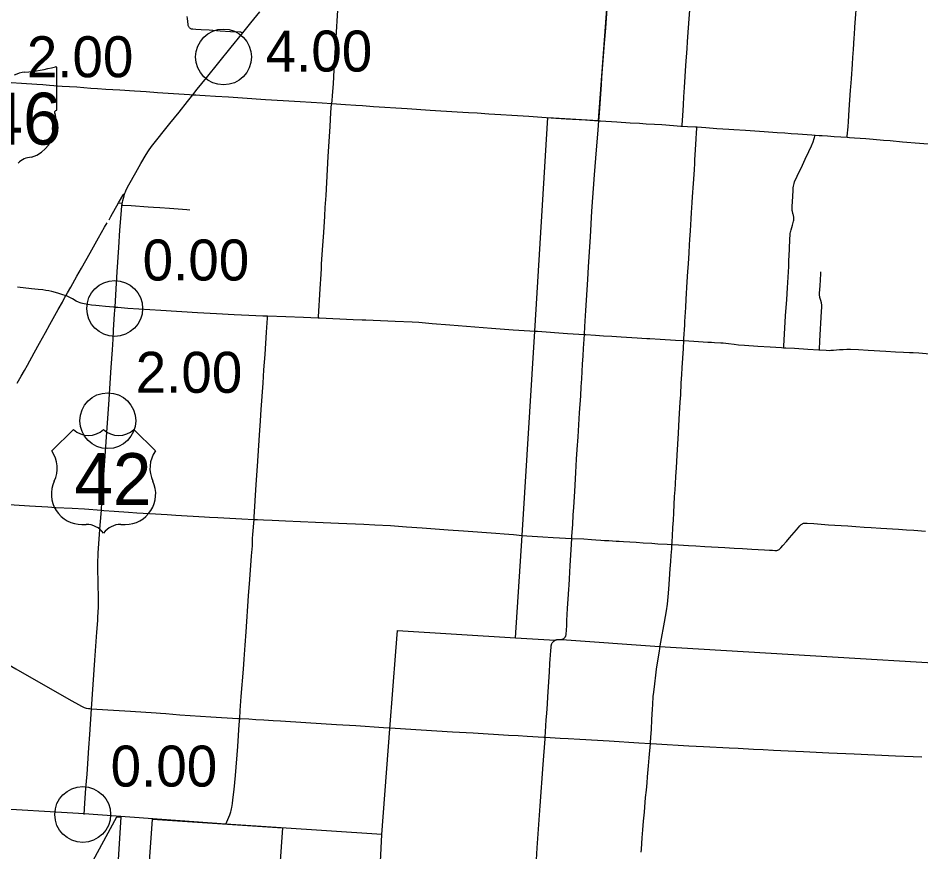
# Model space of a CAD drawing. Extents: x 1813937 to 1948437, y 826606 to 1022856.
# Drawn here: x 1840375 to 1864627, y 879389 to 901785 of the extents above; entities that cross this region are included whole.
import ezdxf

# ---------------------------------------------------------------- set-up
doc = ezdxf.new("R2010")
doc.units = 0
for name, color, linetype in [('Default', 7, 'Continuous'), ('GM_X_Corporation', 7, 'Continuous'), ('GM_X_County', 7, 'Continuous'), ('GM_X_County_Road', 7, 'Continuous'), ('GM_X_State_Route', 7, 'Continuous'), ('GM_X_State_Shield', 7, 'Continuous'), ('GM_X_Township', 7, 'Continuous'), ('GM_X_Township_Road', 7, 'Continuous'), ('GM_X_US_Route', 7, 'Continuous'), ('GM_X_US_Shield', 7, 'Continuous')]:
    doc.layers.add(name, color=color, linetype=linetype)

msp = doc.modelspace()

# ---------------------------------------------------------------- linework, layer by layer
at = {"layer": 'Default'}
for centre in [(1845895, 900740), (1842971, 893987), (1842785, 890971), (1842112, 880395), (1842112, 880395)]:
    msp.add_circle(centre, 750, dxfattribs=at)
at = {"layer": 'GM_X_Corporation'}
for points in [[(1842276, 878944), (1843026, 880333), (1843137, 880326), (1843037, 878758)], [(1843894, 879006), (1843983, 880269), (1847478, 880034), (1847407, 879013)]]:
    msp.add_lwpolyline(points, dxfattribs=at)
at = {"layer": 'GM_X_County'}
msp.add_lwpolyline([(1849106, 864311), (1849634, 872258), (1850017, 877290), (1850147, 879854), (1845959, 880135), (1842150, 880416), (1839410, 880574)], dxfattribs=at)
at = {"layer": 'GM_X_County_Road'}
for points in [[(1858212, 898884), (1858214, 898917), (1858231, 899163), (1858248, 899458), (1858261, 899671), (1858275, 899917), (1858313, 900507), (1858345, 900966), (1858358, 901146), (1858377, 901408), (1858411, 901883), (1858428, 902112), (1858441, 902276), (1858454, 902472), (1858476, 902784), (1858493, 903029), (1858508, 903226), (1858530, 903553), (1858543, 903734), (1858565, 904030)], [(1862739, 899846), (1862745, 899941), (1862761, 900154), (1862770, 900284), (1862779, 900415), (1862787, 900546), (1862798, 900726), (1862812, 900939), (1862834, 901250), (1862840, 901348), (1862854, 901544), (1862879, 901888), (1862912, 902329), (1862927, 902542), (1862942, 902755), (1862964, 903049), (1862969, 903131), (1862980, 903294), (1862992, 903458), (1863006, 903638), (1863012, 903726)], [(1848803, 899489), (1848805, 899500), (1848812, 899560), (1848824, 899707), (1848844, 900018), (1848868, 900395), (1848879, 900591), (1848896, 900853), (1848922, 901263), (1848968, 902000), (1849011, 902721), (1849025, 902966), (1849028, 903004)], [(1855976, 899029), (1855991, 899228), (1856045, 899997), (1856058, 900193), (1856127, 901109), (1856159, 901518), (1856179, 901779), (1856205, 902139), (1856232, 902508)], [(1862645, 898582), (1862647, 898616), (1862668, 898861), (1862679, 899009), (1862701, 899319), (1862739, 899846)], [(1848439, 893732), (1848441, 893763), (1848490, 894516), (1848516, 894909), (1848524, 895057), (1848530, 895171), (1848556, 895564), (1848586, 896023), (1848613, 896465), (1848628, 896694), (1848647, 897022), (1848665, 897366), (1848707, 898070), (1848754, 898873), (1848774, 899250), (1848778, 899288), (1848782, 899332), (1848785, 899370), (1848787, 899396), (1848798, 899459), (1848803, 899489)], [(1854556, 899117), (1854822, 899099), (1855099, 899082), (1855621, 899050), (1855976, 899029)], [(1855588, 893286), (1855600, 893503), (1855626, 893929), (1855679, 894763), (1855701, 895107), (1855747, 895909), (1855791, 896596), (1855857, 897578), (1855893, 898019), (1855957, 898787), (1855976, 899029)], [(1855976, 899029), (1856016, 899027), (1856457, 898998), (1856818, 898973), (1857063, 898958), (1857243, 898947), (1857472, 898934), (1857669, 898922), (1857980, 898900), (1858176, 898886), (1858212, 898884)], [(1858212, 898884), (1858356, 898874), (1858569, 898863), (1858612, 898860)], [(1858257, 893122), (1858260, 893175), (1858281, 893535), (1858288, 893633), (1858296, 893764), (1858310, 894009), (1858324, 894238), (1858350, 894697), (1858367, 894975), (1858382, 895188), (1858397, 895482), (1858411, 895695), (1858420, 895842), (1858434, 896068), (1858444, 896231), (1858455, 896395), (1858465, 896559), (1858473, 896689), (1858483, 896836), (1858493, 896984), (1858500, 897098), (1858509, 897229), (1858523, 897458), (1858540, 897720), (1858551, 897883), (1858557, 897981), (1858573, 898243), (1858591, 898538), (1858601, 898701), (1858609, 898816), (1858612, 898860)], [(1858612, 898860), (1858847, 898844), (1859142, 898822), (1859305, 898811), (1859469, 898801), (1859600, 898793), (1859911, 898774), (1860418, 898739), (1860647, 898723), (1860762, 898715), (1860975, 898700), (1861138, 898688), (1861318, 898674), (1861449, 898666), (1861694, 898648), (1861787, 898642)], [(1861787, 898642), (1861890, 898635), (1861972, 898630), (1862120, 898619), (1862299, 898607), (1862479, 898594), (1862645, 898582)], [(1862645, 898582), (1862708, 898578), (1862839, 898569), (1863150, 898546), (1863347, 898532), (1863624, 898509), (1863804, 898494), (1864131, 898465), (1864588, 898425), (1865046, 898386), (1865307, 898363), (1865387, 898357)], [(1843075, 896824), (1843100, 896869), (1843191, 897024), (1843205, 897042), (1843219, 897058), (1843247, 897084)], [(1842818, 896368), (1842866, 896457), (1843075, 896824)], [(1843075, 896824), (1843090, 896822), (1843154, 896815), (1843172, 896813)], [(1841658, 894328), (1841703, 894404), (1841790, 894557), (1841958, 894857), (1842079, 895071), (1842313, 895484), (1842540, 895881), (1842701, 896166), (1842771, 896286)], [(1840348, 891983), (1840455, 892167), (1840546, 892323), (1840627, 892465), (1840809, 892795), (1840954, 893053), (1841113, 893340), (1841232, 893555), (1841367, 893799), (1841454, 893956), (1841565, 894157), (1841635, 894287), (1841658, 894328)], [(1842980, 894022), (1843052, 894018), (1843328, 893998), (1843917, 893956), (1844212, 893937), (1845194, 893876), (1845702, 893848), (1846177, 893824), (1846571, 893808), (1846948, 893791), (1847079, 893786)], [(1847079, 893786), (1847571, 893768), (1848046, 893749), (1848439, 893732)], [(1848439, 893732), (1848472, 893730), (1849373, 893692), (1849619, 893681), (1849718, 893678), (1850504, 893646), (1850963, 893628), (1851143, 893618), (1851502, 893583), (1851977, 893545), (1852418, 893510), (1853089, 893460), (1853678, 893416), (1854120, 893386), (1854235, 893378)], [(1854235, 893378), (1854324, 893372)], [(1854324, 893372), (1855134, 893316), (1855588, 893286)], [(1855251, 887811), (1855254, 887874), (1855273, 888185), (1855289, 888446), (1855301, 888643), (1855310, 888792), (1855327, 889068), (1855357, 889576), (1855379, 889936), (1855396, 890197), (1855416, 890541), (1855457, 891179), (1855487, 891638), (1855503, 891883), (1855516, 892096), (1855540, 892489), (1855556, 892717), (1855566, 892914), (1855588, 893286)], [(1855588, 893286), (1855623, 893284), (1855885, 893268), (1856098, 893254), (1856328, 893238), (1856574, 893222), (1856722, 893213), (1857001, 893196), (1857132, 893188), (1857263, 893180), (1857345, 893175), (1857624, 893158), (1858035, 893135), (1858232, 893123), (1858257, 893122)], [(1857940, 887644), (1857942, 887692), (1857944, 887725), (1857953, 887872), (1857966, 888101), (1857977, 888297), (1857987, 888494), (1858011, 888936), (1858021, 889116), (1858032, 889279), (1858044, 889476), (1858057, 889705), (1858078, 890049), (1858095, 890343), (1858113, 890638), (1858135, 891014), (1858161, 891473), (1858173, 891669), (1858190, 891980), (1858197, 892094), (1858204, 892209), (1858214, 892389), (1858229, 892651), (1858246, 892913), (1858257, 893122)], [(1837518, 888876), (1837545, 888874), (1837806, 888855), (1838261, 888836), (1838474, 888821), (1838867, 888795), (1839292, 888768), (1839784, 888737), (1840078, 888719), (1840275, 888709), (1840684, 888683), (1841175, 888655), (1841388, 888641), (1841830, 888620), (1842158, 888602), (1842612, 888567)], [(1842612, 888567), (1842682, 888562), (1842959, 888542), (1843342, 888515), (1843566, 888500), (1843907, 888478), (1844381, 888448), (1844612, 888434), (1845383, 888391), (1845514, 888381), (1845742, 888370), (1846382, 888335), (1846715, 888320)], [(1846715, 888320), (1846809, 888316), (1846970, 888307), (1847201, 888298), (1847560, 888281), (1848363, 888247), (1848986, 888220), (1849660, 888189), (1849954, 888172), (1850381, 888154), (1850806, 888125), (1851229, 888095), (1851932, 888042), (1852343, 888014), (1853211, 887951), (1853436, 887929), (1853686, 887911), (1853918, 887892)], [(1853918, 887892), (1854041, 887883), (1854469, 887850), (1854750, 887835), (1855251, 887811)], [(1839753, 884634), (1839900, 884546), (1840313, 884307), (1841735, 883496), (1842075, 883304), (1842113, 883283), (1842148, 883267), (1842176, 883258), (1842206, 883252), (1842265, 883243), (1842304, 883240), (1842349, 883237)]]:
    msp.add_lwpolyline(points, dxfattribs=at)
at = {"layer": 'GM_X_State_Route'}
msp.add_lwpolyline([(1842980, 894022), (1842935, 894024), (1842722, 894040), (1842558, 894052), (1842460, 894062), (1842346, 894078), (1842152, 894108), (1842103, 894117), (1842071, 894126), (1842040, 894137), (1841995, 894156), (1841936, 894185), (1841834, 894240), (1841734, 894295), (1841690, 894316), (1841658, 894328), (1841644, 894334), (1841582, 894353), (1841440, 894394), (1841282, 894437), (1841203, 894456), (1841122, 894471), (1841042, 894483), (1840911, 894498), (1840732, 894516), (1840357, 894561)], dxfattribs=at)
at = {"layer": 'GM_X_State_Shield'}
for p, q in [((1841420, 899335), (1841420, 900441)), ((1841420, 899336), (1841420, 899335))]:
    msp.add_line(p, q, dxfattribs=at)
for centre, major_axis, start_param, end_param in [((1840181, 903270), (3691, 0), 4.814394, 5.042369), ((1841382, 900445), (38.7, 0), 6.141152, 7.989035), ((1840651, 899743), (743, 0), 1.699011, 2.107814), ((1841411, 899254), (60, 0), 1.883978, 3.671073), ((1841379, 899331), (41.5, 0), 5.05454, 6.418171), ((1841559, 898873), (262, 0), 2.387724, 3.262537), ((1841030, 899114), (360, 0), 5.934695, 6.695948), ((1840387, 898732), (923, 0), 5.101752, 6.440018), ((1840777, 897645), (506, 0), 1.647645, 2.488434)]:
    msp.add_ellipse(centre, major_axis=major_axis, ratio=0.8, start_param=start_param, end_param=end_param, dxfattribs=at)
at = {"layer": 'GM_X_Township'}
for points in [[(1853740, 885139), (1853912, 887891), (1854256, 893376), (1854601, 899118), (1855968, 899037), (1856227, 902512), (1856354, 904189), (1858556, 904033), (1863007, 903717), (1863265, 907135), (1863306, 907714), (1863375, 908580), (1863406, 908966), (1863544, 910397), (1864246, 910459), (1864806, 910520), (1866935, 910696), (1872022, 911301), (1871903, 909711), (1873264, 909583), (1874571, 909455), (1879532, 909040), (1882082, 908847)], [(1850147, 879854), (1850364, 882693), (1850523, 884772), (1850567, 885340), (1853740, 885139), (1854805, 885081), (1854864, 885092), (1854977, 885091), (1857606, 884909), (1869894, 884174), (1875339, 883824)]]:
    msp.add_lwpolyline(points, dxfattribs=at)
at = {"layer": 'GM_X_Township_Road'}
for points in [[(1846415, 901392), (1846377, 901399), (1846361, 901402), (1846328, 901405), (1846082, 901418), (1845803, 901436), (1845508, 901456), (1845295, 901468), (1845148, 901476), (1845066, 901483), (1845050, 901486), (1845034, 901491), (1845019, 901497), (1845004, 901504), (1844991, 901513), (1844979, 901524), (1844968, 901537), (1844959, 901551), (1844953, 901566), (1844948, 901582), (1844942, 901614), (1844924, 901776), (1844921, 901824)], [(1839646, 900091), (1839927, 900073), (1840188, 900055), (1840467, 900036), (1840876, 900008), (1841039, 899998), (1841219, 899984), (1841332, 899976)], [(1841332, 899976), (1841432, 899969), (1841562, 899960), (1841955, 899935), (1842326, 899906), (1842505, 899893), (1842735, 899877), (1843111, 899853), (1843504, 899830), (1843667, 899819), (1843814, 899810), (1844125, 899789), (1844976, 899729), (1845025, 899726), (1845066, 899723)], [(1845066, 899723), (1845147, 899721), (1845255, 899713), (1845402, 899702), (1845680, 899685), (1846024, 899665), (1846401, 899642), (1847023, 899602), (1847498, 899572), (1847957, 899544), (1848547, 899506), (1848803, 899489)], [(1848803, 899489), (1849169, 899464), (1849447, 899446), (1849627, 899435), (1849922, 899414), (1850823, 899354), (1851445, 899313), (1852166, 899269), (1852477, 899250), (1852706, 899237), (1853017, 899216), (1853344, 899193), (1853639, 899176), (1854098, 899147), (1854556, 899117)], [(1860939, 892932), (1860942, 892967), (1860943, 892983), (1860961, 893295), (1860992, 893787), (1861021, 894229), (1861038, 894541), (1861074, 895114), (1861081, 895262), (1861096, 895573), (1861109, 895869), (1861113, 895947), (1861114, 895963), (1861115, 895982), (1861117, 896003), (1861122, 896032), (1861124, 896045), (1861128, 896059), (1861138, 896095), (1861177, 896221), (1861205, 896332), (1861211, 896359), (1861213, 896380), (1861214, 896403), (1861213, 896430), (1861211, 896445), (1861207, 896462), (1861204, 896477), (1861200, 896495), (1861193, 896512), (1861187, 896535), (1861182, 896553), (1861177, 896575), (1861173, 896595), (1861171, 896608), (1861169, 896622), (1861167, 896642), (1861166, 896668), (1861166, 896685), (1861167, 896701), (1861168, 896732), (1861175, 896851), (1861192, 897151), (1861197, 897223), (1861203, 897271), (1861210, 897305), (1861218, 897340), (1861234, 897387), (1861300, 897536), (1861442, 897833), (1861519, 897996), (1861617, 898204), (1861687, 898352), (1861731, 898458), (1861763, 898551), (1861772, 898580), (1861780, 898614), (1861787, 898642)], [(1843165, 896763), (1843188, 896762), (1843414, 896751), (1843872, 896717), (1844017, 896706), (1844182, 896694), (1844446, 896676), (1844906, 896640), (1844991, 896635)], [(1861897, 892873), (1861898, 892885), (1861911, 893119), (1861956, 893908), (1861962, 894023), (1861961, 894089), (1861959, 894112), (1861954, 894138), (1861937, 894201), (1861914, 894280), (1861909, 894306), (1861906, 894329), (1861904, 894355), (1861904, 894395), (1861916, 894592), (1861935, 894920), (1861940, 894970)], [(1846715, 888320), (1846719, 888377), (1846774, 889261), (1846809, 889752), (1846864, 890587), (1846889, 890964), (1846909, 891275), (1846957, 891978), (1846981, 892339), (1847009, 892747), (1847050, 893353), (1847075, 893729), (1847076, 893746), (1847079, 893786)], [(1858257, 893122), (1858529, 893106), (1858906, 893083), (1859004, 893078), (1859086, 893075), (1859250, 893065), (1859315, 893060), (1859462, 893042), (1859608, 893024), (1859722, 893012), (1859886, 893000), (1860246, 892977), (1860573, 892955), (1860884, 892935), (1860939, 892932)], [(1860939, 892932), (1860999, 892929), (1861228, 892916), (1861588, 892892), (1861883, 892874), (1861897, 892873)], [(1861897, 892873), (1862079, 892863), (1862161, 892861), (1862210, 892862), (1862276, 892866), (1862439, 892881), (1862537, 892888), (1862636, 892891), (1862734, 892890), (1862947, 892882), (1863209, 892868), (1863684, 892840), (1863946, 892825), (1864159, 892814), (1864323, 892806), (1864421, 892800), (1864568, 892792), (1864764, 892779), (1864961, 892769), (1865027, 892765)], [(1846329, 882975), (1846343, 883190), (1846371, 883566), (1846430, 884302), (1846449, 884564), (1846476, 884940), (1846501, 885300), (1846568, 886266), (1846600, 886708), (1846648, 887346), (1846669, 887608), (1846674, 887722), (1846675, 887804), (1846683, 887919), (1846715, 888320)], [(1857940, 887644), (1857956, 887644), (1858119, 887635), (1858381, 887620), (1858578, 887609), (1858823, 887595), (1859363, 887564), (1859609, 887550), (1859838, 887537), (1860084, 887525), (1860427, 887506), (1860558, 887497), (1860640, 887493), (1860706, 887489), (1860738, 887488), (1860755, 887489), (1860771, 887492), (1860786, 887497), (1860801, 887503), (1860816, 887512), (1860829, 887521), (1860841, 887532), (1860865, 887555), (1860919, 887617), (1861013, 887730), (1861099, 887829), (1861281, 888041), (1861378, 888152), (1861401, 888175), (1861413, 888185), (1861441, 888203), (1861456, 888210), (1861471, 888215), (1861487, 888218), (1861504, 888221), (1861536, 888223), (1861569, 888222), (1861749, 888208), (1862141, 888179), (1862485, 888157), (1862665, 888144), (1862877, 888130), (1863106, 888114), (1863286, 888103), (1863548, 888087), (1864023, 888055), (1864235, 888041), (1864432, 888028), (1864750, 888006)], [(1855117, 885614), (1855123, 885757), (1855135, 885936), (1855150, 886181), (1855169, 886443), (1855177, 886557), (1855186, 886720), (1855206, 887080), (1855232, 887505), (1855251, 887811)], [(1855251, 887811), (1855568, 887797), (1855780, 887781), (1855895, 887774), (1856026, 887764), (1856128, 887758), (1856244, 887751), (1856344, 887745), (1856442, 887739), (1856521, 887734), (1856635, 887727), (1856811, 887716), (1856974, 887706), (1857170, 887692), (1857399, 887678), (1857563, 887667), (1857808, 887651), (1857940, 887644)], [(1857626, 884922), (1857643, 885024), (1857736, 885557), (1857790, 885864), (1857818, 886042), (1857831, 886140), (1857841, 886238), (1857855, 886451), (1857875, 886712), (1857895, 886990), (1857908, 887186), (1857920, 887349), (1857932, 887529), (1857940, 887644)], [(1855098, 885250), (1855098, 885257), (1855100, 885276), (1855102, 885306), (1855113, 885511), (1855117, 885614)], [(1854913, 885099), (1854957, 885098), (1854970, 885098), (1854978, 885098), (1854984, 885099), (1854989, 885100), (1854994, 885101), (1854999, 885103), (1855006, 885106), (1855015, 885111), (1855026, 885117), (1855034, 885123), (1855039, 885126), (1855047, 885133), (1855054, 885139), (1855063, 885150), (1855069, 885157), (1855073, 885164), (1855079, 885175), (1855084, 885187), (1855087, 885197), (1855090, 885206), (1855093, 885217), (1855095, 885232), (1855098, 885250)], [(1854564, 882939), (1854575, 883110), (1854595, 883371), (1854607, 883551), (1854649, 884223), (1854663, 884442), (1854672, 884577), (1854677, 884663), (1854687, 884807), (1854692, 884868), (1854694, 884887), (1854696, 884907), (1854698, 884928), (1854702, 884949), (1854704, 884959), (1854707, 884971), (1854710, 884979), (1854716, 884991), (1854721, 885001), (1854724, 885006), (1854729, 885012), (1854737, 885021), (1854748, 885034), (1854770, 885053), (1854782, 885063), (1854794, 885071), (1854807, 885078), (1854819, 885083), (1854826, 885086), (1854835, 885090), (1854844, 885092), (1854850, 885094), (1854858, 885095), (1854871, 885097), (1854877, 885098), (1854883, 885098), (1854891, 885099), (1854899, 885099), (1854913, 885099)], [(1857362, 882301), (1857363, 882321), (1857373, 882468), (1857386, 882681), (1857401, 882943), (1857416, 883221), (1857424, 883352), (1857438, 883564), (1857448, 883679), (1857475, 883906), (1857504, 884134), (1857525, 884296), (1857566, 884572), (1857602, 884782), (1857626, 884922)], [(1842349, 883237), (1842789, 883208), (1843395, 883168), (1844082, 883122), (1844204, 883114)], [(1844204, 883114), (1844344, 883104), (1844720, 883075), (1845556, 883020), (1846275, 882977), (1846329, 882975)], [(1845958, 880137), (1846066, 880387), (1846093, 880464), (1846103, 880504), (1846112, 880543), (1846119, 880583), (1846128, 880640), (1846134, 880690), (1846146, 880786), (1846176, 881064), (1846212, 881439), (1846274, 882224), (1846297, 882519), (1846317, 882813), (1846329, 882975)], [(1846329, 882975), (1846570, 882962), (1846766, 882949), (1846979, 882935), (1847225, 882921), (1847421, 882907), (1848109, 882864), (1848927, 882815), (1849451, 882781), (1850188, 882733), (1850370, 882722)], [(1854534, 882470), (1854543, 882619), (1854564, 882939)], [(1850370, 882722), (1850779, 882696), (1852040, 882618), (1852597, 882587), (1853546, 882529), (1853808, 882514), (1854054, 882500), (1854496, 882472), (1854534, 882470)], [(1854170, 877091), (1854181, 877254), (1854216, 877794), (1854258, 878481), (1854281, 878858), (1854321, 879496), (1854345, 879872), (1854397, 880624), (1854480, 881736), (1854531, 882423), (1854534, 882470)], [(1854534, 882470), (1854938, 882445), (1855151, 882434), (1855462, 882417), (1856248, 882369), (1857050, 882321), (1857362, 882301)], [(1857113, 879380), (1857119, 879462), (1857141, 879772), (1857157, 879985), (1857176, 880214), (1857198, 880459), (1857208, 880590), (1857232, 880852), (1857251, 881048), (1857269, 881244), (1857284, 881408), (1857308, 881702), (1857328, 881915), (1857362, 882301)], [(1857362, 882301), (1857525, 882291), (1858393, 882241), (1858786, 882221), (1859474, 882186), (1859720, 882174), (1860130, 882154), (1860392, 882138), (1860670, 882122), (1861063, 882102), (1861476, 882083), (1862156, 882051), (1862833, 882020), (1863947, 881970), (1864422, 881951), (1864652, 881943)]]:
    msp.add_lwpolyline(points, dxfattribs=at)
at = {"layer": 'GM_X_US_Route'}
for points in [[(1842980, 894022), (1843011, 894513), (1843037, 894972), (1843078, 895627), (1843108, 896085), (1843124, 896298), (1843150, 896623), (1843162, 896741), (1843165, 896763), (1843168, 896787), (1843172, 896813), (1843176, 896831), (1843187, 896883), (1843221, 897010), (1843238, 897059), (1843247, 897084), (1843261, 897120), (1843272, 897146), (1843301, 897208), (1843352, 897309), (1843538, 897637), (1843676, 897879), (1843814, 898122), (1843876, 898218), (1843963, 898337), (1844453, 898953), (1844699, 899261), (1844922, 899545), (1845066, 899723), (1845189, 899877), (1845436, 900184), (1846097, 901000), (1846376, 901344), (1846415, 901392), (1846627, 901654), (1846866, 901950)], [(1842151, 880391), (1842172, 880696), (1842200, 881105), (1842227, 881482), (1842277, 882185), (1842301, 882545), (1842348, 883233), (1842349, 883237), (1842441, 884542), (1842492, 885295), (1842514, 885609), (1842522, 885716), (1842527, 885812), (1842532, 885983), (1842533, 886180), (1842526, 886623), (1842519, 887000), (1842518, 887115), (1842521, 887230), (1842524, 887314), (1842530, 887426), (1842583, 888162), (1842612, 888567), (1842628, 888784), (1842647, 889054), (1842679, 889521), (1842723, 890143), (1842759, 890666), (1842810, 891403), (1842879, 892401), (1842909, 892877), (1842927, 893161), (1842942, 893400), (1842968, 893842), (1842980, 894022)]]:
    msp.add_lwpolyline(points, dxfattribs=at)
at = {"layer": 'GM_X_US_Shield'}
for p, q in [((1841860, 890739), (1841280, 890159)), ((1844064, 890159), (1843484, 890739)), ((1842092, 888186), (1842208, 888186)), ((1843136, 888186), (1843252, 888186))]:
    msp.add_line(p, q, dxfattribs=at)
for centre, radius, start, end in [((1842266, 891153), 580, 225.573, 314.427), ((1843078, 891153), 580, 225.573, 314.427), ((1840614, 889693), 812, 334.5471, 35.0009), ((1844729, 889693), 812, 144.9991, 205.4529), ((1842083, 888998), 812, 154.8319, 270.6383), ((1843261, 888998), 812, 269.3617, 25.1681), ((1842208, 887606), 580, 36.8699, 90), ((1843136, 887606), 580, 90, 143.1301)]:
    msp.add_arc(centre, radius, start, end, dxfattribs=at)

# ---------------------------------------------------------------- texts
at = {"layer": 'Default'}
for s, p in [('4.00', (1847025, 900349)), ('2.00', (1840610, 900196)), ('0.00', (1843721, 894737)), ('2.00', (1843535, 891721)), ('0.00', (1842862, 881145))]:
    msp.add_text(s, height=1100, dxfattribs=at).set_placement(p)
at = {"layer": 'GM_X_State_Shield'}
msp.add_text('746', height=1392.2, dxfattribs=at).set_placement((1838438, 898388))
at = {"layer": 'GM_X_US_Shield'}
msp.add_text('42', height=1392.2, dxfattribs=at).set_placement((1841888, 888708))

doc.saveas('drawing.dxf')
